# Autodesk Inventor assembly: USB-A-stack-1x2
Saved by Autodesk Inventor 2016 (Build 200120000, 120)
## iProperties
Created: 2018-05
Part Number: USB-A-stack-1x2
Document SubType Name: Assembly
Designer: Administrator
Title: USB-A-stack-1x2 v23
Author: Administrator
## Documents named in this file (4)
- c:\worker\convert-fusion-mar-2018\tmp\job-1\16\output\files\8c58ff39-88bb-4352-afd9-60265520bae5\USB-A-stack-1x2 v23.iam
- c:\worker\convert-fusion-mar-2018\tmp\job-1\16\output\files\8c58ff39-88bb-4352-afd9-60265520bae5\shell.iam
- c:\worker\convert-fusion-mar-2018\tmp\job-1\16\output\files\8c58ff39-88bb-4352-afd9-60265520bae5\Component4.iam
- c:\worker\convert-fusion-mar-2018\tmp\job-1\16\output\files\8c58ff39-88bb-4352-afd9-60265520bae5\leads_1.iam
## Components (3 placed, 3 different names)
1. shell:1 [sub-assembly]
2. Component4:1 [sub-assembly]
3. leads:1 [sub-assembly]
